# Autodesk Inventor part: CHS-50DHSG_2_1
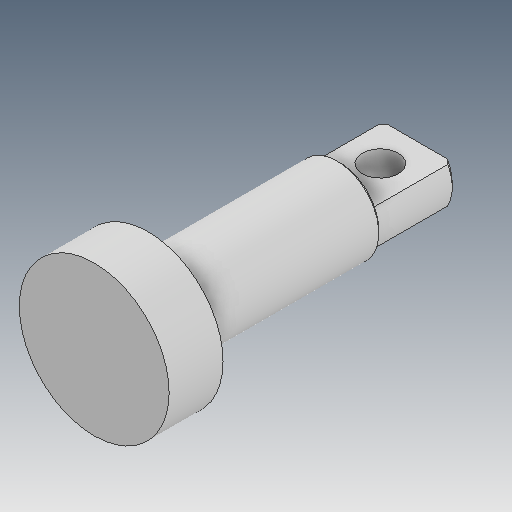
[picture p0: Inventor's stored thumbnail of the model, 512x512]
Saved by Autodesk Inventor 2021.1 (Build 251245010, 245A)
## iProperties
Created: 2019-04
Part Number: CHS-50DHSG_2_1
Material: Ogólny
Document SubType Name: Modeling
Designer: user
Density: 1 g/cm^3
Appearance: Domyślna
Author: user
Revision Number: ÈÎºÎ
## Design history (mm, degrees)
feature "ÊäÈë1"
node "Bryła1"
